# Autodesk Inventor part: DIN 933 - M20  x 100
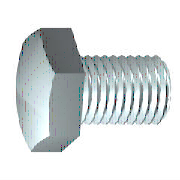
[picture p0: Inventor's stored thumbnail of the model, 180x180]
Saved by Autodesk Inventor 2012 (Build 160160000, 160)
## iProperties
Comments: To add or edit properties for Autodesk Inventor files, use iProperties.
Company: CAD-Verlag
Shininess: 64.0
Length Units: 11269
Angle Units: 11279
Time Units: 11290
Mass Units: 11283
Length Display Precision: 3
Angle Display Precision: 2
Compacted: True
Alert: To add or edit properties for Autodesk Inventor files, use iProperties.
Created: 2004-09
Part Number: DIN 933 - M20  x 100
Vendor: Autodesk Inc.
Document SubType Name: Modeling
Designer: Greiling
Material: Standard
Description: Sechskantschraube
Standard: DIN 933
Size Designation: M20  x 100
Density: 1 g/cm^3
Density: 0.0
Volumn: 0.0
Area: 0.0
PropertySet Name: Model Information
Control State: 0
Master: False
Checked Out: False
EGR: 1
Classification: un/spsc 31161513
Author: Jürgen Kronas
Revision Number: 8
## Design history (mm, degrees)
revolve "Körper" stored, may be unused: angle "d12" = 90 deg
sketch "Skizze2"
  geometry: L1 (0, 17.321)-(15, 8.66); L2 (15, 8.66)-(15, -8.66); L3 (15, -8.66)-(0, -17.321); L4 (0, -17.321)-(-15, -8.66); L5 (-15, -8.66)-(-15, 8.66); L6 (-15, 8.66)-(0, 17.321); 2 further points
  constraints: 12 end point, 1 coincident, 1 vertical, 11 other
  dimensions: "d11" = 30 distance between parallel lines of L5 L2 (= SW)
extrude "Kopf" join sketch "Skizze2" distance "d3" = 11.7 (= KOH - SD); taper "d4" = 0 deg
revolve "Fase1" stored, may be unused: angle "d21" = 90 deg
node "Volumenkörper1"
node "Volumenkörpern"
node "Oberflächenkörpern"
feature "Gewinde" dims "d15" = 92.5 (= GEL), "d16" = 0
chamfer "Fase2" distance "d6" = 1.53363 (= -0.5 x SPD + 0.5 x GD); stored, may be unused: second distance "d7" = 1.53373 (computed from GUL), angle "d55" = 45 deg
sketch "Skizze1"
  geometry: L1 (0, 13.85)-(0, 9.323); L2 (7.5, 10)-(100, 10); L3 (100, 10)-(100, 0); L4 (100, 0)-(-0.8, 0); L5 (-10.88, 0)-(130.24, 0) reference; L6 (-0.8, 0)-(-0.8, 13.85); L7 (-0.8, 13.85)-(0, 13.85); L8 (7.5, 10)-(5.966, 9.323); L9 (5.966, 9.323)-(0, 9.323); L10 (0, -1.385)-(0, 18.005) reference
  constraints: 16 end point, 2 collinear, 2 perpendicular, 1 parallel
  dimensions: "d0" = 100 distance between parallel lines of L3 L1 (= NLG); "d1" = 92.5 distance from line of L2.start L3 (= GEL); "d2" = 20 diameter of L2 L4 (= GD); "d9" = 0.8001 distance between parallel lines of L6 L1 (computed from SD); "d10" = 27.7 diameter of L7 L4 (= SD2); "d13" = 1.53373 horizontal distance of L2.start L8.end (computed from GAL); "d14" = 18.64683 diameter of L9 L4 (= BDM)
sketch "Skizze4"
  geometry: L1 (-12.5, 15)-(-12.5, 17.321); L2 (-12.5, 17.321)-(-11.16, 17.321); L3 (-11.16, 17.321)-(-12.5, 15); L4 (-13.67, 0)-(2.71, 0) reference; L5 (-0.8, 17.321)-(-12.5, 17.321) reference; L6 (-12.5, 8.66)-(-12.5, 17.321) reference
  constraints: 6 end point, 2 collinear, 1 perpendicular, 1 vertical
  dimensions: "d5" = 30 deg angle of L3 L1 (= ANG1); "d19" = 30 diameter of L1.start L4 (= SW0)
other parameters: "NLG" = 100 [user parameter; used in 2 equation terms], "GD" = 20 (= NND) [user parameter; used in 2 equation terms], "BDM" = 18.64683 [user parameter; used in 1 equation term], "KOH" = 12.5 [user parameter; used in 1 equation term], "GEL" = 92.5 [user parameter; used in 2 equation terms], "SW" = 30 [user parameter; used in 2 equation terms], "SW0" = 30 [user parameter; used in 1 equation term], "SPD" = 16.93275 (= NND - 1.2269 x TPU) [user parameter; used in 1 equation term], "SD2" = 27.7 [user parameter; used in 1 equation term], "SD" = 0.8 [user parameter; used in 2 equation terms], "ANG1" = 30 deg [user parameter; used in 1 equation term], "GAL" = 1.53363 (= 0.61345 x TPU) [user parameter; used in 1 equation term], "GUL" = 1.53363 (= 0.61345 x TPU) [user parameter; used in 1 equation term], "d8" = 0, "RR" = 0.8 [user parameter], "E0" = 34.65 (= 1.155 x SW) [user parameter], "TPU" = 2.5 [user parameter; used in 5 equation terms], "GD1" = 16.93275 (= THREADDIA - 1.2269 x TPU) [user parameter], "PTC" = 2.5 (= TPU) [user parameter], "TOA" = 30 deg [user parameter]
